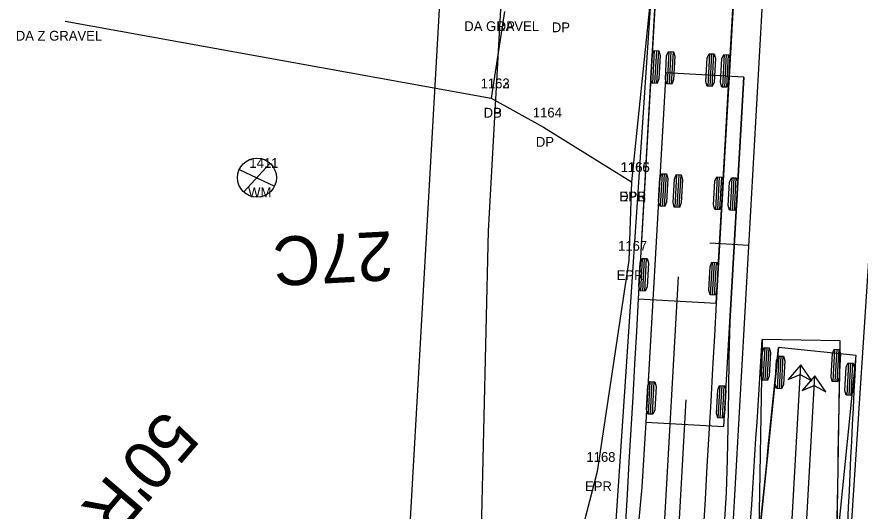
# Model space of a CAD drawing. Extents: x 1812113 to 1819860, y 1177290 to 1181185.
# Drawn here: x 1813594.3 to 1813680.6, y 1178825.8 to 1178876.4 of the extents above; entities that cross this region are included whole.
import ezdxf

# ---------------------------------------------------------------- set-up
doc = ezdxf.new("R2010")
doc.units = 0
for name, color, linetype in [('RD_EX_Driveway', 7, 'Continuous'), ('RD_EX_Driveway_txCode', 7, 'Continuous'), ('RD_EX_Road', 7, 'Continuous'), ('RD_EX_Road_txCode', 7, 'Continuous'), ('RD_EX_RW', 7, 'Continuous'), ('RD_EX_UT', 7, 'Continuous'), ('RD_EX_UT_txCode', 7, 'Continuous'), ('RD_HC_CL', 7, 'Continuous'), ('RD_HC_Data_Tic', 7, 'Continuous'), ('RD_PD_ALT1_TrvlWay', 7, 'Continuous'), ('RD_PD_ALT3_TnTmp', 7, 'Continuous'), ('RD_PD_CstnLmt', 7, 'Continuous'), ('RD_Sketch5', 7, 'Continuous'), ('RD_Sketch7', 7, 'Continuous'), ('RD_Sketch8', 7, 'Continuous'), ('RD_Sketch9', 7, 'Continuous'), ('RD_SMD_Locator', 7, 'Continuous')]:
    doc.layers.add(name, color=color, linetype=linetype)

msp = doc.modelspace()

# ---------------------------------------------------------------- linework, layer by layer
at = {"layer": 'RD_EX_Driveway'}
for p, q in [((1813644.178, 1178876.902), (1813642.834, 1178868.045)), ((1813599.198, 1178875.923), (1813642.834, 1178868.045)), ((1813642.834, 1178868.045), (1813648.184, 1178865.061)), ((1813648.184, 1178865.061), (1813657.189, 1178859.476))]:
    msp.add_line(p, q, dxfattribs=at)
at = {"layer": 'RD_EX_Road'}
for p, q in [((1813659.53, 1178882.118), (1813657.189, 1178859.476)), ((1813657.189, 1178859.476), (1813656.912, 1178851.422)), ((1813656.912, 1178851.422), (1813653.668, 1178829.816)), ((1813653.668, 1178829.816), (1813648.43, 1178809.526))]:
    msp.add_line(p, q, dxfattribs=at)
at = {"layer": 'RD_EX_RW'}
msp.add_line((1813632.03, 1178780.068), (1813647.583, 1179054.502), dxfattribs=at)
at = {"layer": 'RD_EX_UT'}
for p, q in [((1813617.496, 1178858.44), (1813620.164, 1178861.337)), ((1813617.015, 1178860.736), (1813620.646, 1178859.023))]:
    msp.add_line(p, q, dxfattribs=at)
msp.add_circle((1813618.848, 1178859.898), 2, dxfattribs=at)
at = {"layer": 'RD_HC_CL'}
msp.add_line((1813663.556, 1178753.116), (1813680.53, 1179052.635), dxfattribs=at)
at = {"layer": 'RD_HC_Data_Tic'}
msp.add_line((1813669.214, 1178852.956), (1813665.22, 1178853.182), dxfattribs=at)
at = {"layer": 'RD_PD_ALT1_TrvlWay'}
for p, q in [((1813655.439, 1178821.971), (1813662.128, 1178921.747)), ((1813678.744, 1178809.043), (1813685.223, 1178908.833))]:
    msp.add_line(p, q, dxfattribs=at)
at = {"layer": 'RD_PD_CstnLmt'}
for p, q in [((1813642.544, 1178854.467), (1813648.111, 1178954.312)), ((1813641.818, 1178822.743), (1813642.544, 1178854.467))]:
    msp.add_line(p, q, dxfattribs=at)
at = {"layer": 'RD_Sketch5'}
for p, q in [((1813672.244, 1178842.513), (1813668.622, 1178806.897)), ((1813680.203, 1178841.704), (1813672.244, 1178842.513)), ((1813672.244, 1178842.513), (1813672.244, 1178842.513)), ((1813672.29, 1178841.641), (1813672.102, 1178838.313)), ((1813672.498, 1178841.629), (1813672.31, 1178838.301)), ((1813672.706, 1178841.617), (1813672.518, 1178838.289)), ((1813676.581, 1178806.088), (1813680.203, 1178841.704)), ((1813679.423, 1178840.953), (1813679.234, 1178837.625)), ((1813679.631, 1178840.941), (1813679.442, 1178837.613)), ((1813679.839, 1178840.929), (1813679.65, 1178837.601)), ((1813672.794, 1178783.581), (1813675.97, 1178839.621))]:
    msp.add_line(p, q, dxfattribs=at)
for points in [[(1813670.381, 1178824.196), (1813670.546, 1178825.817), (1813670.711, 1178827.442), (1813670.877, 1178829.071), (1813671.043, 1178830.702), (1813671.209, 1178832.336), (1813671.375, 1178833.973), (1813671.542, 1178835.611), (1813671.709, 1178837.252), (1813671.876, 1178838.894), (1813672.043, 1178840.538), (1813672.21, 1178842.184), (1813672.244, 1178842.513)], [(1813679.345, 1178824.46), (1813679.426, 1178826.16), (1813679.507, 1178827.857), (1813679.589, 1178829.552), (1813679.673, 1178831.245), (1813679.756, 1178832.936), (1813679.841, 1178834.625), (1813679.926, 1178836.313), (1813680.012, 1178837.999), (1813680.098, 1178839.684), (1813680.185, 1178841.367), (1813680.203, 1178841.704)]]:
    msp.add_lwpolyline(points, dxfattribs=at)
for points in [[(1813672.238, 1178841.644), (1813672.757, 1178841.614), (1813672.887, 1178841.14), (1813672.752, 1178838.744), (1813672.57, 1178838.286), (1813672.05, 1178838.316), (1813671.92, 1178838.79), (1813672.055, 1178841.187)], [(1813679.372, 1178840.956), (1813679.891, 1178840.926), (1813680.021, 1178840.452), (1813679.884, 1178838.056), (1813679.701, 1178837.599), (1813679.182, 1178837.628), (1813679.052, 1178838.103), (1813679.189, 1178840.499)], [(1813675.97, 1178839.621), (1813674.665, 1178838.106), (1813675.914, 1178838.623), (1813677.096, 1178837.968)]]:
    msp.add_lwpolyline(points, close=True, dxfattribs=at)
at = {"layer": 'RD_Sketch7'}
for p, q in [((1813670.575, 1178843.323), (1813669.969, 1178807.528)), ((1813678.574, 1178843.188), (1813670.575, 1178843.323)), ((1813670.575, 1178843.323), (1813670.575, 1178843.323)), ((1813677.968, 1178807.393), (1813678.574, 1178843.188)), ((1813670.836, 1178842.509), (1813670.648, 1178839.181)), ((1813671.044, 1178842.497), (1813670.856, 1178839.169)), ((1813671.252, 1178842.485), (1813671.064, 1178839.157)), ((1813678.001, 1178842.354), (1813677.812, 1178839.026)), ((1813678.209, 1178842.342), (1813678.02, 1178839.015)), ((1813678.417, 1178842.331), (1813678.228, 1178839.003)), ((1813671.346, 1178784.53), (1813674.532, 1178840.756))]:
    msp.add_line(p, q, dxfattribs=at)
for points in [[(1813669.399, 1178824.699), (1813669.511, 1178826.401), (1813669.621, 1178828.101), (1813669.73, 1178829.798), (1813669.839, 1178831.494), (1813669.946, 1178833.188), (1813670.053, 1178834.881), (1813670.159, 1178836.572), (1813670.264, 1178838.261), (1813670.368, 1178839.95), (1813670.472, 1178841.637), (1813670.575, 1178843.323)], [(1813678.266, 1178825.007), (1813678.294, 1178826.648), (1813678.322, 1178828.292), (1813678.349, 1178829.939), (1813678.377, 1178831.589), (1813678.405, 1178833.24), (1813678.433, 1178834.894), (1813678.461, 1178836.55), (1813678.489, 1178838.207), (1813678.518, 1178839.866), (1813678.546, 1178841.526), (1813678.574, 1178843.188)]]:
    msp.add_lwpolyline(points, dxfattribs=at)
for points in [[(1813670.784, 1178842.512), (1813671.303, 1178842.482), (1813671.433, 1178842.007), (1813671.298, 1178839.611), (1813671.115, 1178839.154), (1813670.596, 1178839.183), (1813670.466, 1178839.658), (1813670.601, 1178842.054)], [(1813677.949, 1178842.357), (1813678.469, 1178842.328), (1813678.598, 1178841.853), (1813678.462, 1178839.457), (1813678.279, 1178839), (1813677.76, 1178839.029), (1813677.63, 1178839.504), (1813677.766, 1178841.9)], [(1813674.532, 1178840.756), (1813673.227, 1178839.241), (1813674.475, 1178839.757), (1813675.658, 1178839.103)]]:
    msp.add_lwpolyline(points, close=True, dxfattribs=at)
at = {"layer": 'RD_Sketch8'}
for p, q in [((1813659.912, 1178883.232), (1813657.886, 1178847.49)), ((1813665.874, 1178847.037), (1813667.899, 1178882.78)), ((1813659.535, 1178872.904), (1813659.347, 1178869.576)), ((1813659.743, 1178872.892), (1813659.555, 1178869.564)), ((1813659.951, 1178872.88), (1813659.763, 1178869.552)), ((1813661.033, 1178872.819), (1813660.844, 1178869.491)), ((1813661.241, 1178872.807), (1813661.052, 1178869.479)), ((1813661.449, 1178872.795), (1813661.26, 1178869.467)), ((1813665.193, 1178872.583), (1813665.004, 1178869.255)), ((1813665.401, 1178872.571), (1813665.212, 1178869.243)), ((1813665.609, 1178872.559), (1813665.42, 1178869.231)), ((1813666.69, 1178872.498), (1813666.502, 1178869.17)), ((1813666.898, 1178872.486), (1813666.71, 1178869.158)), ((1813667.106, 1178872.475), (1813666.918, 1178869.147)), ((1813658.142, 1178848.31), (1813658.33, 1178851.638)), ((1813658.35, 1178848.298), (1813658.538, 1178851.626)), ((1813658.558, 1178848.286), (1813658.746, 1178851.614)), ((1813665.297, 1178847.904), (1813665.485, 1178851.232)), ((1813665.505, 1178847.893), (1813665.693, 1178851.221)), ((1813665.713, 1178847.881), (1813665.901, 1178851.209)), ((1813657.822, 1178775.655), (1813662.021, 1178849.759)), ((1813657.886, 1178847.49), (1813665.874, 1178847.037)), ((1813665.874, 1178847.037), (1813665.874, 1178847.037))]:
    msp.add_line(p, q, dxfattribs=at)
for points in [[(1813659.709, 1178879.658), (1813659.507, 1178876.084), (1813659.304, 1178872.509), (1813659.102, 1178868.935), (1813658.899, 1178865.361), (1813658.697, 1178861.787), (1813658.494, 1178858.212), (1813658.291, 1178854.638), (1813658.089, 1178851.064), (1813657.886, 1178847.49), (1813657.886, 1178847.49), (1813657.886, 1178847.49), (1813657.697, 1178844.152), (1813657.508, 1178840.814), (1813657.319, 1178837.476), (1813657.13, 1178834.137), (1813656.941, 1178830.799), (1813656.751, 1178827.461), (1813656.562, 1178824.123)], [(1813667.697, 1178879.205), (1813667.494, 1178875.631), (1813667.291, 1178872.057), (1813667.089, 1178868.483), (1813666.886, 1178864.908), (1813666.684, 1178861.334), (1813666.481, 1178857.76), (1813666.279, 1178854.185), (1813666.076, 1178850.611), (1813665.874, 1178847.037), (1813665.874, 1178847.037), (1813665.684, 1178843.699), (1813665.495, 1178840.361), (1813665.306, 1178837.023), (1813665.117, 1178833.685), (1813664.928, 1178830.347), (1813664.739, 1178827.009), (1813664.549, 1178823.671)]]:
    msp.add_lwpolyline(points, dxfattribs=at)
for points in [[(1813659.484, 1178872.907), (1813660.003, 1178872.877), (1813660.133, 1178872.402), (1813659.997, 1178870.006), (1813659.814, 1178869.549), (1813659.295, 1178869.579), (1813659.165, 1178870.053), (1813659.301, 1178872.45)], [(1813660.981, 1178872.822), (1813661.5, 1178872.792), (1813661.63, 1178872.318), (1813661.495, 1178869.921), (1813661.312, 1178869.464), (1813660.793, 1178869.494), (1813660.663, 1178869.969), (1813660.798, 1178872.365)], [(1813665.141, 1178872.586), (1813665.66, 1178872.557), (1813665.79, 1178872.082), (1813665.655, 1178869.686), (1813665.472, 1178869.229), (1813664.953, 1178869.258), (1813664.823, 1178869.733), (1813664.958, 1178872.129)], [(1813666.639, 1178872.501), (1813667.158, 1178872.472), (1813667.288, 1178871.997), (1813667.152, 1178869.601), (1813666.969, 1178869.144), (1813666.45, 1178869.173), (1813666.32, 1178869.648), (1813666.456, 1178872.044)], [(1813658.609, 1178848.283), (1813658.09, 1178848.313), (1813657.96, 1178848.788), (1813658.096, 1178851.184), (1813658.279, 1178851.641), (1813658.798, 1178851.611), (1813658.928, 1178851.137), (1813658.792, 1178848.74)], [(1813665.764, 1178847.878), (1813665.245, 1178847.907), (1813665.115, 1178848.382), (1813665.251, 1178850.778), (1813665.434, 1178851.235), (1813665.953, 1178851.206), (1813666.083, 1178850.731), (1813665.947, 1178848.335)]]:
    msp.add_lwpolyline(points, close=True, dxfattribs=at)
at = {"layer": 'RD_Sketch9'}
for p, q in [((1813660.7, 1178870.628), (1813658.674, 1178834.885)), ((1813668.687, 1178870.175), (1813660.7, 1178870.628)), ((1813666.662, 1178834.433), (1813668.687, 1178870.175)), ((1813660.323, 1178860.299), (1813660.135, 1178856.971)), ((1813660.531, 1178860.288), (1813660.343, 1178856.96)), ((1813660.739, 1178860.276), (1813660.551, 1178856.948)), ((1813661.821, 1178860.215), (1813661.632, 1178856.887)), ((1813662.029, 1178860.203), (1813661.84, 1178856.875)), ((1813662.237, 1178860.191), (1813662.048, 1178856.863)), ((1813665.981, 1178859.979), (1813665.792, 1178856.651)), ((1813666.189, 1178859.967), (1813666, 1178856.639)), ((1813666.397, 1178859.955), (1813666.208, 1178856.627)), ((1813667.479, 1178859.894), (1813667.29, 1178856.566)), ((1813667.687, 1178859.882), (1813667.498, 1178856.554)), ((1813667.895, 1178859.87), (1813667.706, 1178856.542)), ((1813658.93, 1178835.706), (1813659.118, 1178839.034)), ((1813659.138, 1178835.694), (1813659.326, 1178839.022)), ((1813659.346, 1178835.682), (1813659.534, 1178839.01)), ((1813666.085, 1178835.3), (1813666.273, 1178838.628)), ((1813666.293, 1178835.288), (1813666.481, 1178838.616)), ((1813666.501, 1178835.277), (1813666.689, 1178838.605)), ((1813661.488, 1178813.827), (1813662.81, 1178837.155)), ((1813658.674, 1178834.885), (1813666.662, 1178834.433)), ((1813666.662, 1178834.433), (1813666.662, 1178834.433))]:
    msp.add_line(p, q, dxfattribs=at)
for points in [[(1813660.7, 1178870.628), (1813660.497, 1178867.054), (1813660.295, 1178863.479), (1813660.092, 1178859.905), (1813659.89, 1178856.331), (1813659.687, 1178852.757), (1813659.485, 1178849.182), (1813659.282, 1178845.608), (1813659.08, 1178842.034), (1813658.877, 1178838.46), (1813658.674, 1178834.885), (1813658.674, 1178834.885), (1813658.674, 1178834.885), (1813658.476, 1178831.553), (1813658.241, 1178828.224), (1813657.939, 1178824.9)], [(1813668.687, 1178870.175), (1813668.485, 1178866.601), (1813668.282, 1178863.027), (1813668.08, 1178859.453), (1813667.877, 1178855.878), (1813667.674, 1178852.304), (1813667.472, 1178848.73), (1813667.284, 1178845.155), (1813667.174, 1178841.575), (1813667.132, 1178837.987), (1813667.071, 1178834.395), (1813667.071, 1178834.395), (1813667.005, 1178831.038), (1813666.885, 1178827.677), (1813666.688, 1178824.319)]]:
    msp.add_lwpolyline(points, dxfattribs=at)
for points in [[(1813660.272, 1178860.302), (1813660.791, 1178860.273), (1813660.921, 1178859.798), (1813660.785, 1178857.402), (1813660.602, 1178856.945), (1813660.083, 1178856.974), (1813659.953, 1178857.449), (1813660.089, 1178859.845)], [(1813661.769, 1178860.218), (1813662.289, 1178860.188), (1813662.419, 1178859.713), (1813662.283, 1178857.317), (1813662.1, 1178856.86), (1813661.581, 1178856.89), (1813661.451, 1178857.364), (1813661.587, 1178859.76)], [(1813665.929, 1178859.982), (1813666.449, 1178859.952), (1813666.579, 1178859.478), (1813666.443, 1178857.081), (1813666.26, 1178856.624), (1813665.741, 1178856.654), (1813665.611, 1178857.129), (1813665.747, 1178859.525)], [(1813667.427, 1178859.897), (1813667.946, 1178859.867), (1813668.076, 1178859.393), (1813667.94, 1178856.997), (1813667.758, 1178856.539), (1813667.238, 1178856.569), (1813667.108, 1178857.044), (1813667.244, 1178859.44)], [(1813659.397, 1178835.679), (1813658.878, 1178835.709), (1813658.748, 1178836.183), (1813658.884, 1178838.579), (1813659.067, 1178839.037), (1813659.586, 1178839.007), (1813659.716, 1178838.532), (1813659.58, 1178836.136)], [(1813666.552, 1178835.274), (1813666.033, 1178835.303), (1813665.903, 1178835.778), (1813666.039, 1178838.174), (1813666.222, 1178838.631), (1813666.741, 1178838.602), (1813666.871, 1178838.127), (1813666.735, 1178835.731)]]:
    msp.add_lwpolyline(points, close=True, dxfattribs=at)
at = {"layer": 'RD_SMD_Locator'}
for centre in [(1813599.198, 1178875.923), (1813642.834, 1178868.045), (1813642.834, 1178868.045), (1813648.184, 1178865.061), (1813657.189, 1178859.476), (1813657.189, 1178859.476), (1813656.912, 1178851.422), (1813653.668, 1178829.816)]:
    msp.add_circle(centre, 0.001, dxfattribs=at)

# ---------------------------------------------------------------- texts
at = {"layer": 'RD_EX_Driveway_txCode'}
for s, p in [('DA GRAVEL', (1813640.075, 1178874.902)), ('DP', (1813643.398, 1178874.902)), ('DP', (1813649.042, 1178874.783)), ('DA Z GRAVEL', (1813594.151, 1178873.923)), ('1162', (1813641.748, 1178869.045)), ('1163', (1813641.748, 1178869.045)), ('DB', (1813642.055, 1178866.045)), ('DP', (1813642.055, 1178866.045)), ('1164', (1813647.097, 1178866.061)), ('DP', (1813647.404, 1178863.061)), ('1165', (1813656.103, 1178860.476)), ('DPB', (1813655.937, 1178857.476))]:
    msp.add_text(s, height=1, dxfattribs=at).set_placement(p)
at = {"layer": 'RD_EX_Road_txCode'}
for s, p in [('1166', (1813656.079, 1178860.476)), ('EPR', (1813655.961, 1178857.476)), ('1167', (1813655.825, 1178852.422)), ('EPR', (1813655.683, 1178849.422)), ('1168', (1813652.581, 1178830.816)), ('EPR', (1813652.44, 1178827.816))]:
    msp.add_text(s, height=1, dxfattribs=at).set_placement(p)
at = {"layer": 'RD_EX_UT_txCode'}
for s, p in [('1411', (1813618.069, 1178860.898)), ('WM', (1813617.943, 1178857.898))]:
    msp.add_text(s, height=1, dxfattribs=at).set_placement(p)
at = {"layer": 'RD_PD_ALT3_TnTmp'}
msp.add_text("50'R", height=5, rotation=229.38478, dxfattribs=at).set_placement((1813609.408, 1178836.329))
at = {"layer": 'RD_PD_CstnLmt'}
msp.add_text('27C', height=5, rotation=182.94638, dxfattribs=at).set_placement((1813632.64, 1178854.423))

doc.saveas('drawing.dxf')
